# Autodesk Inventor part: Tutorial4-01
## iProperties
Created: 2009-05
Part Number: Tutorial4-01
Document SubType Name: Modeling
Designer: Sham
Density: 1 g/cm^3
Author: Sham
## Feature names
1. Extrusion1
2. Fillet2
